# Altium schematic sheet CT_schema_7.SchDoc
size 277 x 170 mm
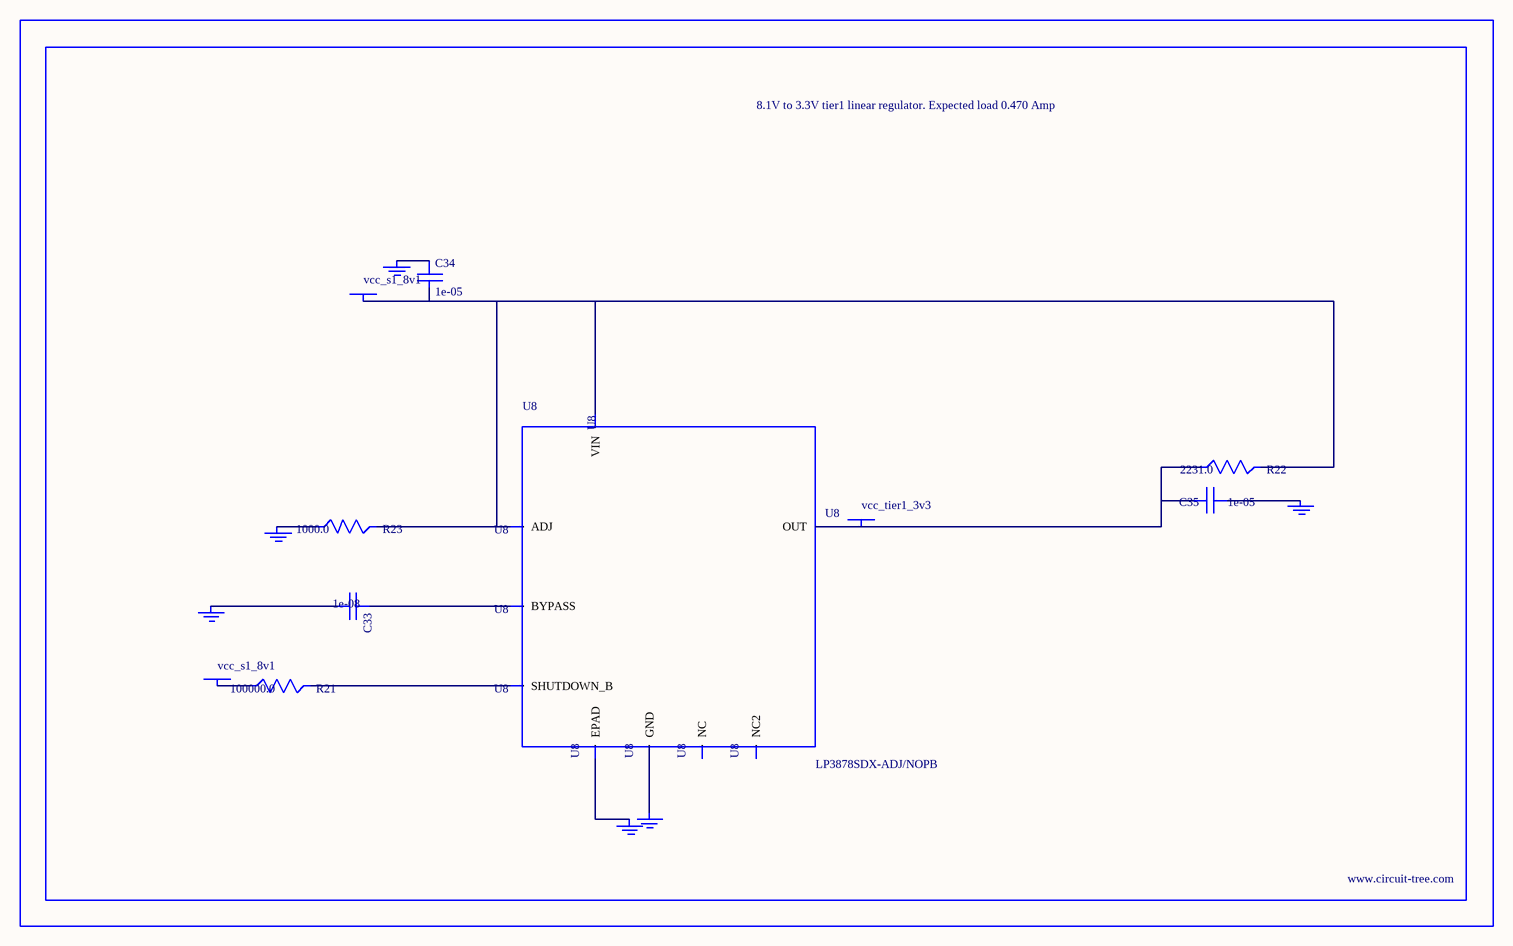
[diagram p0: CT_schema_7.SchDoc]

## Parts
BORDER6  (no value)
C33  1e-08  [C0402]
C34  1e-05  [C1206]
C35  1e-05  [C1210]
GND_INSTANCE_6_0  (no value)
GND_INSTANCE_6_1  (no value)
GND_INSTANCE_6_2  (no value)
GND_INSTANCE_6_3  (no value)
GND_INSTANCE_6_4  (no value)
GND_INSTANCE_6_5  (no value)
POWER_INSTANCE_6_0  vcc_s1_8v1
POWER_INSTANCE_6_1  vcc_s1_8v1
POWER_INSTANCE_6_2  vcc_tier1_3v3
R21  100000.0  [R0603]
R22  2231.0  [R0603]
R23  1000.0  [R0603]
U8  LP3878SDX-ADJ/NOPB  [WSON-8]

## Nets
NetC33_1: C33.1 U8.1(BYPASS)
NetC33_2: C33.2 GND_INSTANCE_6_0.0(GND)
NetC34_1: C34.1 GND_INSTANCE_6_1.0(GND)
NetC34_2: C34.2 POWER_INSTANCE_6_0.0(PWR) R22.2 R23.2 U8.4(VIN) U8.6(ADJ)
NetC35_1: C35.1 GND_INSTANCE_6_2.0(GND)
NetC35_2: C35.2 POWER_INSTANCE_6_2.0(PWR) R22.1 U8.5(OUT)
NetGND_INSTANCE_6_3_0: GND_INSTANCE_6_3.0(GND) R23.1
NetGND_INSTANCE_6_4_0: GND_INSTANCE_6_4.0(GND) U8.PAD(EPAD)
NetGND_INSTANCE_6_5_0: GND_INSTANCE_6_5.0(GND) U8.3(GND)
NetPOWER_INSTANCE_6_1_0: POWER_INSTANCE_6_1.0(PWR) R21.1
NetR21_2: R21.2 U8.8(SHUTDOWN_B)

Not connected (* = marked no-connect by the designer): U8 2(NC) 7(NC2)

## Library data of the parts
BORDER6 = BORDER_PAGE6
C33 = C0402C103K3RAC
C34 = C1206C106K3RACTU
C35 = GRM32DR61E106MA12L
GND_INSTANCE_6_0-GND_INSTANCE_6_5 = GND
POWER_INSTANCE_6_0-POWER_INSTANCE_6_2 = PWR
R21 = RC0603JR-07100KL
R22 = R22
R23 = RC0603JR-071KL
